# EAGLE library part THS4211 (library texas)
LOW-DISTORTION, HIGH-SPEED, VOLTAGE FEEDBACK AMPLIFIER Source: http://focus.ti.com/lit/ds/symlink/ths4211.pdf
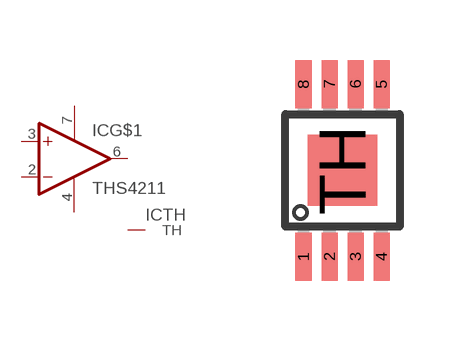
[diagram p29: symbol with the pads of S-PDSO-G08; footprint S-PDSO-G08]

Designator prefix IC; gates G$1=OPAMP+- TH=THERMAL

## THS4211 (MF: TEXAS INSTRUMENT CONNECTORS; MPN: THS4211DGK; OC_FARNELL: 8453306; OC_NEWARK: 95H4489)  [S-PDSO-G08]
2  G$1:-IN  in
3  G$1:+IN  in
4  G$1:V-  pwr
6  G$1:OUT  out
7  G$1:V+  pwr
TH  TH:TH  pas

## Footprint S-PDSO-G08 (pad centres in mm)
DGN (S-PDSO-G8) PowerPAD (TM) Plastic Small-Outline Package Source: http://focus.ti.com/lit/ds/symlink/ths4211.pdf
smd 0.4 x 1.2: 1 -0.975,-2.157; 2 -0.325,-2.157; 3 0.325,-2.157; 4 0.975,-2.157; 5 0.975,2.157; 6 0.325,2.157; 7 -0.325,2.157; 8 -0.975,2.157
smd 1.73 x 1.78: TH 0,0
